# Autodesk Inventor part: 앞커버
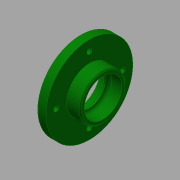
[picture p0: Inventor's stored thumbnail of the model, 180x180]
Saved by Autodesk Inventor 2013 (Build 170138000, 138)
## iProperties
Created: 2015-09
Part Number: 앞커버
Material: 알루미늄 6061
Document SubType Name: Modeling
Designer: mduedu
Density: 2.71 g/cm^3
Mass: 58.9874 g
Surface Area: 98.7754 cm^2
Volume: 21.7666 cm^3
Author: mduedu
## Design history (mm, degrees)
sketch "스케치1"
  geometry: L1 (-4, 67)-(-16, 67); L2 (-16, 67)-(-16, 85); L3 (-16, 85)-(-24, 85); L4 (-24, 85)-(-24, 70.5); L5 (-27, 70.5)-(-27, 61); L6 (-27, 61)-(-4, 61); L7 (-4, 61)-(-4, 67); L8 (-79.5, 39.5)-(-79.5, 54.5) reference; L9 (48.5, 54.5)-(48.5, 39.5) reference; L10 (-79.5, 47)-(48.5, 47); L11 (-24, 70.5)-(-27, 70.5); 3 further points
  constraints: 18 end point, 6 parallel, 4 midpoint, 1 horizontal, 1 perpendicular, 1 vertical alignment
  dimensions: "d0" = 23 distance between parallel lines of L7 L5; "d2" = 28 diameter of L6 L10; "d3" = 40 diameter of L1 L10; "d5" = 12 distance of L1.start L1.end; "d6" = 76 diameter of L3 L10; "d7" = 8 distance of L2.end L3.end; "d8" = 47 diameter of L4.end L10
revolve "회전1" sketch "스케치1" stored, may be unused: angle "d4" = 90 deg
sketch "스케치2"
  geometry: C1 r 38 at (0, 0) reference; 2 further points
  constraints: 1 coincident
hole "구멍1" sketch "스케치2" at (0, 0) diameter "d11" = 33; stored, may be unused: countersink angle "d15" = 90 deg, drill point angle "d17" = 0 deg; dims "d12" = 6, "d13" = 4, "d14" = 2, "d16" = 12
fillet "모깎기1" dims "d18" = 3
fillet "모깎기2" dims "d19" = 1
sketch "스케치3"
  geometry: C1 r 38 at (0, 0) reference; 2 further points
  constraints: 1 coincident
hole "구멍2" sketch "스케치3" at (0, 0) diameter "d20" = 40; stored, may be unused: countersink angle "d24" = 90 deg, drill point angle "d26" = 0 deg; dims "d21" = 6, "d22" = 4, "d23" = 2, "d25" = 8.4
fillet "모깎기3" dims "d27" = 0.4
chamfer "모따기1" distance "d28" = 0.8; stored, may be unused: second distance "d29" = 2, angle "d30" = 30 deg
chamfer "모따기2" distance "d61" = 1; stored, may be unused: second distance "d62" = 2, angle "d63" = 45 deg
sketch "스케치7" dims "d56" = 58
  geometry: C1 r 38 at (0, 0) reference; 5 further points
  constraints: 2 vertical alignment, 1 coincident, 7 other
  dimensions: "d59" = 360 deg dimension on C1.centre point (0, 29) (derived)
sketch "스케치8"
  geometry: 4 further points
  constraints: 4 other
hole "구멍5" sketch "스케치8" at (-29, 0), (0, -29), (29, 0), (0, 29) diameter "d64" = 4.5; stored, may be unused: countersink angle "d68" = 90 deg, drill point angle "d70" = 0 deg; dims "d65" = 6, "d66" = 8, "d67" = 4.6, "d69" = 8
chamfer "모따기3" distance "d71" = 1; stored, may be unused: second distance "d72" = 2, angle "d73" = 45 deg
node "솔리드1"
node "참조1"
node "참조2"
